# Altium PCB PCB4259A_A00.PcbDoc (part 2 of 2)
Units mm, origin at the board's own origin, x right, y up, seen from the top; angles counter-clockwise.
Board outline 30 x 45 mm, 4 copper layers (Top Layer, Signal Layer 2, Signal Layer 3, Bottom Layer), stack 1.606 mm thick; 90 components, 88 nets, 336 pads, 378 vias.
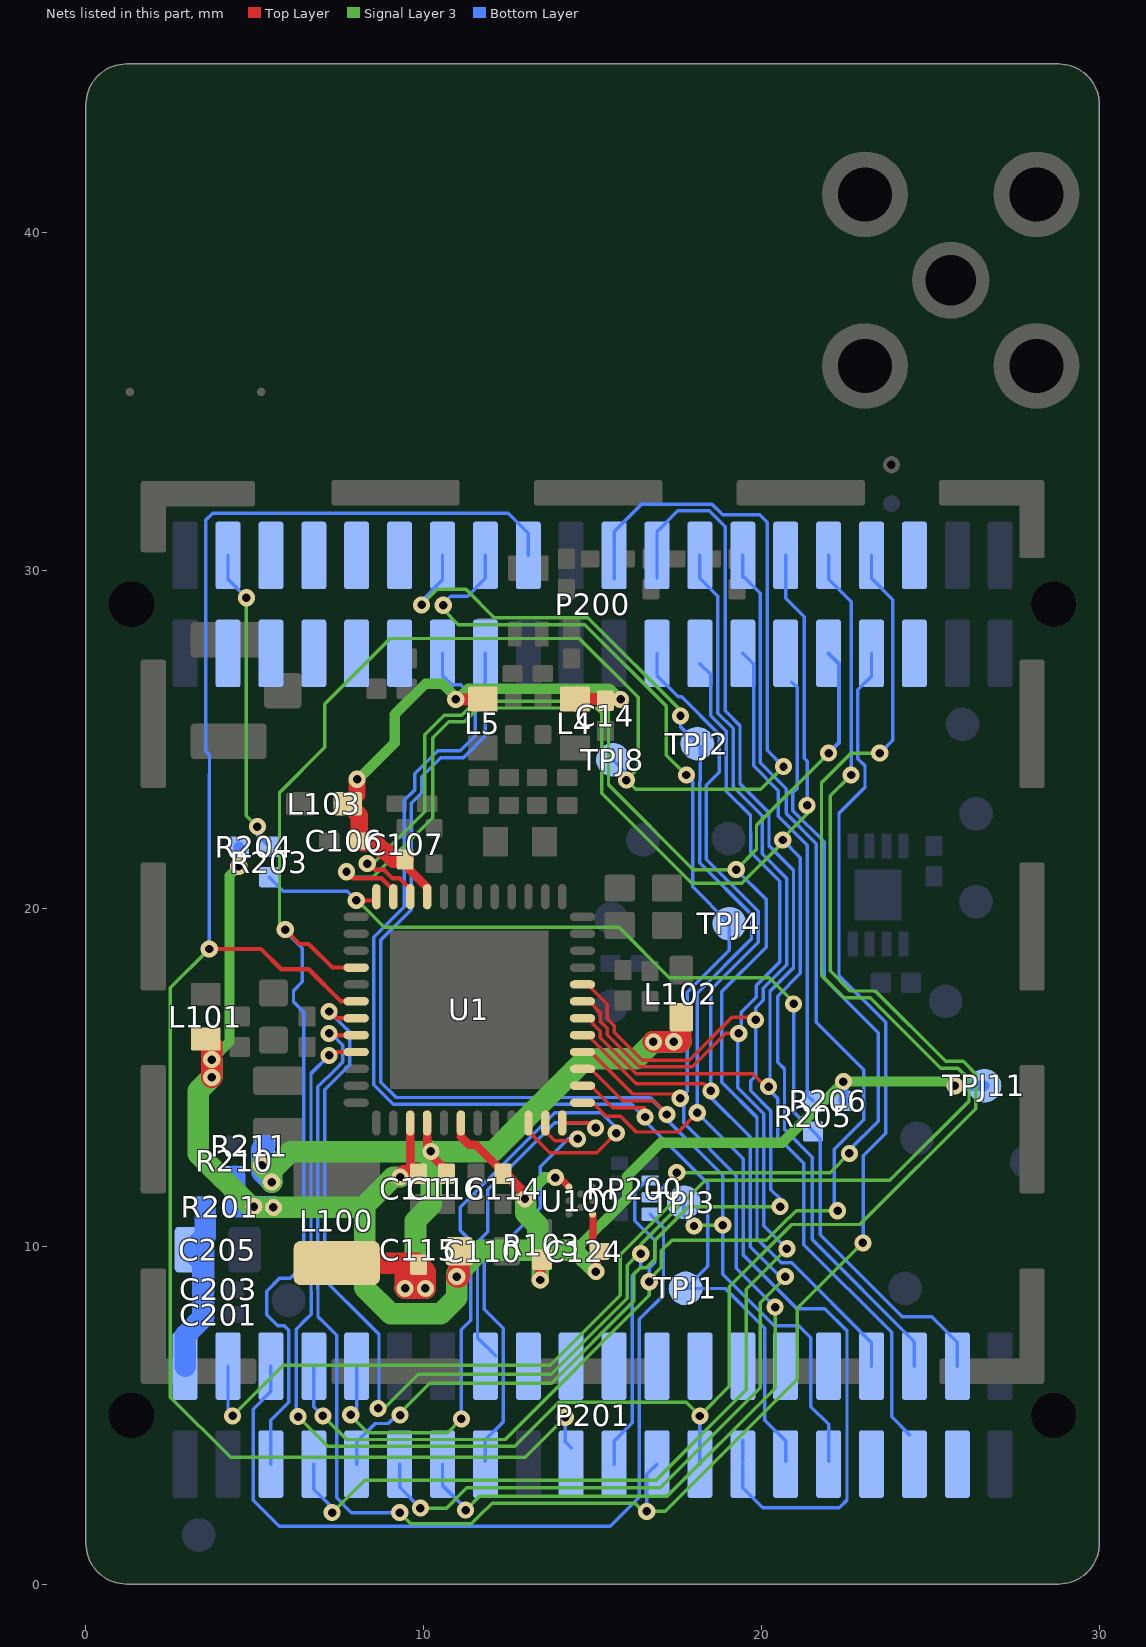
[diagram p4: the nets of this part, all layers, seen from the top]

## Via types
v1: diameter 0.508, hole 0.25, Top Layer to Bottom Layer, tented both sides, 376 vias
v2: diameter 0.5, hole 0.25, Top Layer to Bottom Layer, tented both sides, 2 vias

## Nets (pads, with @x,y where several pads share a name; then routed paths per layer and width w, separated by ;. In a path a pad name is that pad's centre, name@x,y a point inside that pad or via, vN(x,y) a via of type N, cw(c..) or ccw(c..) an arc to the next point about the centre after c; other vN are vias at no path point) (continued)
RADIO_PA3: P200.22 P201.5 TPJ8.1 U1.28 | length 61
  Top Layer w0.102: v1(16,23.8) 16.15,23.8 v1@16.187,23.763
  Top Layer w0.127: v1(5.9,19.375) 6.325,18.95 6.598,18.95 7.298,18.25 U1.28@8,18.25
  Signal Layer 3 w0.102: v1(5.9,19.375) 5.73,19.545 5.73,23.43 7.075,24.775 7.075,26.052 9.013,27.991 14.609,27.991 16.35,26.25 16.35,24.15 v1(16,23.8) 16.275,23.525 19.975,23.525 v1(20.65,24.2)
  Bottom Layer w0.102: P201.5@5.475,3.55 5.475,4.855 5.997,5.377 5.997,7.3 ; v1@5.975,19.25 6.406,18.818 6.406,17.831 6.144,17.568 6.144,17.232 6.45,16.925 6.45,9.45 6.052,9.052 5.73,9.052 5.348,8.67 5.348,7.977 5.673,7.652 5.865,7.652 6,7.517 6,7.3 ; TPJ8.1@15.6,24.7 TPJ8.1@15.6,24.4 16.1,23.9 16.1,23.766 16.066,23.8 v1(16,23.8) ; P200.22@15.635,29.765 P200.22@15.635,30.45 15.635,31.16 16.447,31.972 18.533,31.972 18.852,31.652 19.948,31.652 20.171,31.429 20.171,24.679 v1(20.65,24.2)
RADIO_PA5: P200.18 P201.19 U1.30 | length 55.9
  Top Layer w0.127: v1(3.65,18.8) 5.184,18.8 5.784,18.2 6.598,18.2 7.548,17.25 U1.30@8,17.25
  Signal Layer 3 w0.102: v1(3.65,18.8) 2.5,17.65 2.5,5.533 4.283,3.75 13,3.75 v1(14.188,4.938)
  Bottom Layer w0.102: v1(3.65,18.8) 3.65,23.975 3.656,23.982 3.656,24.544 3.55,24.65 3.55,31.5 3.75,31.7 12.5,31.7 13.095,31.105 P200.18@13.095,30.45 ; v1(14.188,4.938) 14.188,4.215 P201.19@14.365,4.038
RADIO_PB11: P200.34 P201.21 U1.31 | length 62.7
  Top Layer w0.127: v1(7.198,16.95) 7.248,16.95 7.448,16.75 U1.31@8,16.75
  Signal Layer 3 w0.102: v1@8.737,5.112 9.837,6.213 13.769,6.213 16.022,8.466 16.022,9.443 16.354,9.775 v1(16.426,9.775) 16.426,10.051 18.327,11.952 23.8,11.952 26.14,14.292 26.14,14.95 25.815,15.275 25.3,15.275 23.222,17.353 22.447,17.353 21.775,18.025 21.775,23.727 22.648,24.6 v1(23.5,24.6)
  Bottom Layer w0.102: v1(7.198,16.95) 7.604,16.544 7.606,16.544 7.808,16.342 7.808,15.37 7.075,14.638 7.075,8.998 7.711,8.361 7.714,8.361 8.675,7.4 8.675,5.225 v1(8.65,5.2) ; P201.21@15.635,3.55 15.635,4.235 16.175,4.775 16.175,9.125 16.426,9.376 v1(16.426,9.775) ; P200.34@23.255,30.45 23.255,29.771 23.881,29.145 23.881,24.981 v1(23.5,24.6)
RADIO_PB12: P200.33 P201.23 U1.32 | length 56.6
  Top Layer w0.127: v1(7.198,16.3) 7.248,16.25 U1.32@8,16.25
  Signal Layer 3 w0.102: v1(9.288,2.113) 9.618,1.782 11.407,1.782 11.525,1.9 11.644,2.02 12.022,2.397 16.253,2.397 16.6,2.05 v1(16.6,2.15) 17.15,2.15 21.063,6.062 21.063,8.163 v1(23,10.1)
  Bottom Layer w0.102: v1(7.198,16.3) v1@7.224,16.274 ; v1@7.25,16.3 7.254,16.3 7.604,15.95 7.604,15.454 7.391,15.241 6.865,14.715 6.865,8.747 6.869,8.744 6.869,7.919 7.043,7.744 7.422,7.366 7.422,2.551 7.86,2.113 v1(9.288,2.113) ; v1(16.6,2.15) 16.6,3.245 P201.23@16.905,3.55 ; v1(23,10.1) 23.006,10.106 23.006,12.681 23.675,13.35 23.675,16.625 22.294,18.006 22.294,22.818 23.063,23.588 23.063,24.225 22.853,24.435 22.853,26.478 23.255,26.88 P200.33@23.255,27.55
RADIO_PB13: P200.32 P201.25 U1.33 | length 59.4
  Top Layer w0.127: v1(7.198,15.65) 7.198,15.7 7.148,15.75 U1.33@8,15.75
  Signal Layer 3 w0.102: v1(6.282,4.956) 7.162,4.075 12.69,4.075 14,5.385 17.765,5.385 v1(18.175,4.975) 19.05,5.85 19.05,8.8 20.894,10.644 22.912,10.644 26.344,14.075 26.344,15.1 25.965,15.478 25.447,15.478 23.37,17.556 22.631,17.556 22.036,18.15 22.036,23.336 v1(22.65,23.95)
  Bottom Layer w0.102: v1@6.223,5.086 6.223,7.548 6.499,7.824 6.665,7.99 6.665,8.661 6.662,8.663 6.662,15.114 v1(7.198,15.65) ; P201.25@18.175,3.55 v1(18.175,4.975) ; P200.32@21.985,30.45 21.985,29.741 22.65,29.076 v1(22.65,23.95)
RADIO_PC9: P201.10 U1.46 | length 21.1
  Top Layer w0.102: U1.46@13.1,13.65 13.1,13.4 13.729,12.771 15.119,12.771 v1(15.698,13.35)
  Signal Layer 3 w0.102: v1(7.838,5.013) 7.838,4.988 8.345,4.482 10.707,4.482 v1(11.113,4.888)
  Bottom Layer w0.102: v1(7.838,5.013) 8.015,5.19 P201.10@8.015,6.45 ; v1@11.113,4.934 11.113,7.533 11.387,7.807 11.387,10.163 11.084,10.466 11.084,11.159 13.875,13.95 15.25,13.95 15.698,13.502 v1(15.698,13.35)
RADIO_PC10: P201.15 U1.47 | length 12.6
  Top Layer w0.102: U1.47@13.6,13.65 13.6,13.4 13.877,13.123 14.5,13.123 v1(14.555,13.177)
  Bottom Layer w0.102: P201.15@11.825,3.635 11.825,4.275 12.347,4.797 12.347,7.578 11.794,8.131 11.794,9.494 13.444,11.144 13.444,12.071 13.454,12.082 13.454,12.354 14.277,13.177 v1(14.555,13.177)
RADIO_PC11: P201.16 U1.48 | length 10.4
  Top Layer w0.102: U1.48@14.098,13.65 U1.48@14.1,13.65 14.944,13.65 v1(15.088,13.505)
  Bottom Layer w0.102: P201.16@12.131,6.756 11.59,7.297 11.59,10.115 11.9,10.425 11.9,11.677 13.873,13.65 14.944,13.65 v1(15.088,13.505)
RADIO_PD13: P200.31 P201.34 U1.22 | length 44.8
  Top Layer w0.127: v1(8.325,21.326) 8.372,21.326 8.557,21.142 8.827,21.142 9.079,20.89 9.286,20.89 9.598,20.578 U1.22@9.598,20.35
  Signal Layer 3 w0.102: v1(8.325,21.326) 8.496,21.326 10.033,22.863 10.033,25.146 10.612,25.725 11.122,25.725 11.534,26.137 15.188,26.137 15.469,25.856 15.469,23.656 17.975,21.15 v1(19.25,21.15) 19.85,21.75 19.85,22.465 v1(21.985,24.6)
  Bottom Layer w0.102: v1(19.25,21.15) 20.134,20.266 20.134,18.85 18.825,17.541 18.825,14.853 19.866,13.812 19.866,10.221 20.581,9.506 20.894,9.506 23.255,7.145 P201.34@23.255,6.45
  Bottom Layer w0.127: v1(21.985,24.6) 22.294,24.909 22.294,27.241 P200.31@21.985,27.55
RADIO_PD14: P200.30 P201.36 U1.23 | length 51.6
  Top Layer w0.127: v1(7.713,21.087) 7.906,20.894 8.751,20.894 9.098,20.548 U1.23@9.1,20.35
  Signal Layer 3 w0.102: v1(7.713,21.087) 7.71,21.087 7.7,21.076 7.857,20.92 8.494,20.92 ; 10.25,22.676 8.494,20.92 ; v1(21.35,23.05) 21.35,22.8 20.626,22.076 v1(20.626,22.026) 20.626,21.951 19.418,20.744 17.931,20.744 15.265,23.41 15.265,25.772 15.104,25.934 11.618,25.934 11.206,25.522 10.734,25.522 10.262,25.049 10.262,22.687 8.494,20.92
  Bottom Layer w0.102: v1(20.626,22.026) 21.15,21.502 21.15,18.079 20.475,17.404 20.475,15.45 20.679,15.246 20.679,13.459 21.5,12.638 21.5,10.2 24.525,7.175 P201.36@24.525,6.45 ; P200.30@20.715,30.45 20.715,29.185 21.259,28.641 21.259,25.353 21.26,24.453 21.35,24.362 v1(21.35,23.05)
RADIO_PD15: P201.38 R203.1 R205.1 U1.24 | length 31
  Top Layer w0.127: v1(8,20.238) 8.486,20.238 U1.24@8.598,20.35
  Signal Layer 3 w0.102: v1(8,20.238) 8.03,20.238 8.828,19.439 15.78,19.439 17.271,17.948 20.227,17.948 20.95,17.225 v1(20.95,17.175)
  Bottom Layer w0.102: R203.1@5.425,20.925 5.844,20.506 7.732,20.506 v1(8,20.238) ; v1(20.95,17.175) 20.95,13.975 R205.1@21.525,13.4 21.739,13.186 21.739,10.339 24.164,7.913 25.038,7.913 25.795,7.156 P201.38@25.795,6.45
RADIO_PF0: P200.14 P201.27 TPJ2.1 U1.1 | length 47
  Top Layer w0.102: U1.1@14.698,14.25 U1.1@14.7,14.25 14.998,14.25 15.398,13.85 15.824,13.85 16.292,13.382 17.53,13.382 v1(18.098,13.95)
  Signal Layer 3 w0.102: v1(9.938,28.988) 10.4,29.45 11.25,29.45 12.093,28.607 14.855,28.607 17.6,25.862 v1(17.6,25.7)
  Bottom Layer w0.102: v1(9.938,28.988) 9.938,29.113 10.555,29.73 P200.14@10.555,30.45 ; v1(17.6,25.7) 17.6,25.38 TPJ2.1@18.1,24.88 18.181,24.799 18.181,23.782 18.164,23.765 18.164,21.358 19.702,19.82 19.702,19.1 18.094,17.491 18.094,13.954 v1(18.098,13.95) 19.46,12.588 19.46,9.74 21.05,8.15 21.877,8.15 22.529,7.498 22.529,2.488 22.304,2.263 20.038,2.263 19.445,2.856 P201.27@19.445,3.55 ; P201.27@19.445,3.635 P201.27@19.445,4.255
RADIO_PF1: P200.13 P201.29 TPJ1.1 U1.2 | length 38.6
  Top Layer w0.102: U1.2@14.7,14.75 14.948,14.75 15.598,14.1 16.548,14.1
  Bottom Layer w0.102: 9.725,23.975 9.731,23.981 ; P200.13@10.555,27.55 10.555,26.885 10.82,26.619 11.1,26.619 11.525,26.194 11.525,25.114 11.074,24.663 10.413,24.663 9.731,23.981 ; v1@16.548,13.8 16.548,13.715 18.406,11.857 18.406,9.406 TPJ1.1@17.75,8.75 18.926,8.75 20.1,7.576 20.1,4.85 20.715,4.235 P201.29@20.715,3.635 ; v1@16.55,13.8 16.15,14.2 9.1,14.2 8.525,14.775 8.525,19.15 9.425,20.05 9.425,23.2 9.731,23.507 9.731,23.981
  other v1: 16.551,13.826
RADIO_PF2: P200.15 P201.31 TPJ3.1 U1.3 | length 40.7
  Top Layer w0.102: U1.3@14.7,15.25 14.948,15.25 15.895,14.303 16.797,14.303 v1(17.2,13.9)
  Signal Layer 3 w0.102: v1(18,10.6) 18.029,10.629 18.033,10.625 v1(18.85,10.625)
  Bottom Layer w0.102: P200.15@11.825,27.55 11.825,25.109 11.176,24.46 10.498,24.46 9.935,23.897 9.935,23.422 9.628,23.116 9.628,19.966 8.728,19.066 8.728,14.859 9.184,14.403 16.697,14.403 ; 16.75,14.35 16.697,14.403 ; TPJ3.1@17.7,11.3 17.7,10.9 v1(18,10.6) ; P201.31@21.985,3.635 21.985,4.725 21.463,5.248 21.463,7.295 21.105,7.652 20.373,7.652 18.85,9.175 v1(18.85,10.625) 18.85,12.1 17.2,13.75 v1(17.2,13.9) 16.697,14.403
RADIO_PF3: P200.16 P201.13 TPJ4.1 U1.4 | length 48.7
  Top Layer w0.102: U1.4@14.698,15.75 U1.4@14.7,15.75 14.948,15.75 16.192,14.506 17.466,14.506 v1(17.593,14.38)
  Signal Layer 3 w0.102: v1(10.576,28.976) 10.576,28.855 11.027,28.404 14.771,28.404 17.182,25.993 17.182,24.534 17.766,23.95 v1(17.775,23.95) ; v1(11.238,2.188) 11.65,2.6 17.2,2.6 20.4,5.8 v1(20.4,8.2)
  Bottom Layer w0.102: P201.13@10.555,3.55 10.555,2.918 11.238,2.235 v1(11.238,2.188) ; v1(10.576,28.976) 10.576,29.025 10.798,29.248 11.298,29.248 11.825,29.775 P200.16@11.825,30.45 ; v1(17.775,23.95) 17.775,23.941 17.961,23.755 17.961,20.639 TPJ4.1@19.05,19.55 19.05,18.769 17.806,17.525 17.806,14.593 v1(17.593,14.38) 17.692,14.281 17.692,13.65 19.256,12.085 19.256,9.344 v1(20.4,8.2)
RADIO_PF4: P200.23 P201.11 U1.5 | length 42.9
  Top Layer w0.102: U1.5@14.698,16.25 U1.5@14.7,16.25 14.85,16.25 16.285,14.815 18.285,14.815 v1(18.5,14.6)
  Signal Layer 3 w0.102: v1(9.9,2.25) 10.675,2.25 11.275,2.85 17,2.85 19.957,5.807 19.957,8.331 20.725,9.1 v1(20.7,9.1)
  Bottom Layer w0.102: P201.11@9.285,3.55 9.285,2.865 v1(9.9,2.25) ; P200.23@16.905,27.55 16.905,26.895 17.531,26.269 17.633,26.269 18.752,25.15 18.752,24.029 18.368,23.644 18.368,21.458 19.906,19.92 19.906,19 18.5,17.594 v1(18.5,14.6) ; v1@18.504,14.6 18.504,14.4 19.663,13.242 19.663,9.987 20.55,9.1 v1(20.7,9.1)
RADIO_PF5: P200.24 P201.35 U1.6 | length 40.1
  Top Layer w0.102: U1.6@14.8,16.8 14.9,16.8 15,16.7 15,16.592 15.227,16.365 15.227,16.173 16.295,15.105 19.745,15.105 20.124,14.726 v1(20.209,14.726)
  Bottom Layer w0.102: P200.24@16.905,29.771 P200.24@16.905,30.45 16.905,31.155 17.519,31.769 18.449,31.769 18.923,31.295 18.923,25.852 19.362,25.413 19.362,23.688 20.22,22.83 20.22,21.855 20.947,21.128 20.947,18.247 20.251,17.551 20.251,14.769 v1(20.209,14.726) 20.209,14.641 20.476,14.374 20.476,13.225 21.247,12.453 21.247,10.05 23.849,7.449 23.849,4.952 P201.35@24.388,4.413
RADIO_PF6: P200.25 P201.7 U1.7 | length 45.6
  Top Layer w0.102: U1.7@14.698,17.25 U1.7@14.7,17.25 14.898,17.25 15.227,16.921 15.227,16.652 15.431,16.449 15.431,16.257 16.379,15.308 17.946,15.308 18.937,16.3 v1(19.325,16.3)
  Signal Layer 3 w0.102: v1(7.285,2.113) 8.247,3.075 16.875,3.075 19.55,5.75 19.55,8.725 v1(20.75,9.925)
  Bottom Layer w0.102: P201.7@6.745,3.55 6.745,2.805 7.285,2.265 v1(7.285,2.113) ; P200.25@18.175,27.25 18.494,26.931 18.494,25.706 18.956,25.244 18.956,23.47 19.672,22.753 19.672,22.253 19.675,22.25 19.675,21.669 20.54,20.803 20.54,18.415 19.845,17.719 19.845,17.37 19.4,16.925 19.4,16.375 v1(19.325,16.3) 19.29,16.265 19.29,14.697 20.069,13.919 20.069,10.606 v1(20.75,9.925)
RADIO_PF7: P200.26 P201.9 U1.8 | length 45.3
  Top Layer w0.102: v1@9.25,5.05 v1(9.3,5) ; U1.8@14.7,17.75 14.842,17.75 15.431,17.162 15.431,16.736 15.634,16.533 15.634,16.341 16.463,15.512 17.862,15.512 19.125,16.775 19.75,16.775 v1(19.825,16.7)
  Signal Layer 3 w0.102: v1(9.3,5) 9.3,5.071 10.179,5.95 13.794,5.95 16.225,8.381 16.225,9.187 16.407,9.369 16.594,9.369 16.832,9.607 16.832,10.17 17.837,11.175 v1(20.55,11.175) ; v1@19.625,16.7 v1(19.825,16.7)
  Bottom Layer w0.102: P201.9@8.015,3.55 8.015,4.209 8.559,4.752 8.952,4.752 9.2,5 v1(9.3,5) ; P200.26@18.175,30.45 18.175,29.776 18.706,29.245 18.706,25.781 19.159,25.329 19.159,23.604 20.016,22.746 20.016,21.615 20.744,20.887 20.744,18.331 20.048,17.635 20.048,17.286 19.825,17.063 v1(19.825,16.7) 19.825,15.05 19.675,14.9 19.675,14.6 20.272,14.003 20.272,11.678 20.55,11.4 v1(20.55,11.175)
USB_VBUS: P200.35
USB_VREG: P200.36
VBIAS: C14.1 C106.1 C107.1 L4.1 L5.1 L103.2 U1.21 | length 17.1
  Top Layer w0.254: C107.1@9.386,21.337 10.098,20.625 U1.21@10.098,20.35
  Top Layer w0.356: v1(10.947,26.187) L5.1@11.563,26.187 ; L4.1@14.475,26 L4.1@14.575,26.1 ; L4.1@14.475,26.2 15.325,26.2 C14.1@15.375,26.15 ; C14.1@15.375,26.188 v1(15.828,26.188)
  Top Layer w0.508: v1(8.025,23.825) 8.025,23.375 L103.2@7.75,23.1 8.09,22.76 8.09,22.01 C106.1@8.1,22 8.164,21.936 8.578,21.936 8.819,21.694 8.867,21.694 9.112,21.45 C107.1@9.45,21.45
  Signal Layer 3 w0.305: v1@8.066,23.825 9.144,24.902 9.144,25.744 10.052,26.652 10.555,26.652 v1@10.954,26.253 ; v1(10.947,26.187) 10.997,26.187 11.31,26.5 15.5,26.5 v1@15.91,26.089
VDCDC: C115.1 C116.1 L100.2 L102.1 R211.2 U1.40 | length 29.2
  Top Layer w0.254: U1.40@10.098,13.65 v1@10.098,12.821 ; v1(10.21,12.806) 10.194,12.821 v1@10.098,12.821 ; C116.1@10.675,12.15 10.675,12.244 v1@10.098,12.821
  Top Layer w0.635: L100.2@7.398,9.5 C115.1@9.798,9.5 ; v1(16.8,16.05) 17.602,16.05 17.602,16.749 L102.1@17.628,16.775 ; C115.1@9.798,9.5 10.048,9.25 v1(10.048,8.75) v1(9.448,8.75) 9.448,9.15 C115.1@9.798,9.5
  Signal Layer 3 w0.635: v1(5.2,12.4) v1@5.5,12.1 ; v1(5.5,11.9) v1@5.5,12.1 ; v1@10.003,8.795 9.748,9.05 ; v1(10.048,8.75) v1(9.448,8.75) 9.748,9.05 ; v1@10.225,12.806 v1@10.225,12.8 ; v1@17.629,16.05 v1(16.8,16.05) 16.3,15.55 14.798,15.55 12.948,13.7 12.048,12.8 v1@10.225,12.8 ; v1@5.5,12.1 5.5,12.25 6.05,12.8 v1@10.225,12.8 ; 9.748,9.05 9.748,10.748 10.225,11.225 v1@10.225,12.8
  Bottom Layer w0.635: R211.2@5.3,12.975 5.2,12.875 v1(5.2,12.4) 5.2,12.2 v1(5.5,11.9)
  other v1: 17.399,16.053
VMCU: C110.1 C111.1 C114.1 C124.1 L101.1 R103.1 R201.2 R204.1 R206.1 R210.2 TPJ11.1 U1.39 U1.42 U100.A1 U100.E3 | length 59
  Top Layer w0.203: v1(13.898,12.034) 14.014,12.034 U100.E3@14.298,11.75 ; U100.A1@14.998,10.95 15.01,10.938 15.01,10.281 14.998,10.269 14.998,9.95 C124.1@15.098,9.85
  Top Layer w0.254: U1.39@9.598,13.65 9.598,12.4 C111.1@9.848,12.15 ; U1.42@11.098,13.65 11.098,13.25 11.348,13 11.548,13 C114.1@12.348,12.2
  Top Layer w0.305: C114.1@12.348,12.2 12.998,11.55 v1(12.998,11.4) ; v1(13.45,9) 13.45,9.55 R103.1@13.5,9.6 ; v1(15.098,9.25) C124.1@15.098,9.85
  Top Layer w0.508: v1(9.298,12.05) 9.398,12.15 C111.1@9.848,12.15
  Top Layer w0.635: L101.1@3.55,16.135 3.725,15.96 v1(3.725,15.525) v1(3.725,15) ; v1(10.976,9.1) 11.05,9.1 C110.1@11.05,9.85
  Signal Layer 3 w0.305: v1(3.725,15.525) 4.25,16.05 4.25,20.975 v1(4.525,21.25) ; 13.4,9.875 13.45,9.825 ; 14.473,9.875 16.025,11.427 16.025,12.075 17.011,13.061 20.611,13.061 v1(22.425,14.875) 25.6,14.875 v1(25.725,14.75)
  Signal Layer 3 w0.33: v1(12.998,11.4) 12.998,11.464 13.568,12.034 v1(13.898,12.034)
  Signal Layer 3 w0.508: v1(13.45,9) 13.45,9.825 ; 14.473,9.875 v1(15.098,9.25)
  Signal Layer 3 w0.635: v1(3.725,15.525) v1(3.725,15) 3.325,14.6 3.325,12.733 4.883,11.175 v1(4.975,11.175) 5,11.15 v1(5.55,11.15) 8.196,11.15 8.248,11.202 ; v1(9.298,12.05) 9.096,12.05 8.248,11.202 ; v1(12.998,11.4) 13.021,11.377 13.021,10.977 13.375,10.623 13.375,10.221 13.4,10.196 13.4,9.875 ; 14.473,9.875 13.4,9.875 ; 8.248,11.202 8.248,8.775 9.023,8 10.5,8 10.976,8.476 v1(10.976,9.1) 10.976,9.176 11.675,9.875 13.4,9.875
  Bottom Layer w0.305: v1(4.525,21.25) R204.1@4.525,21.825 ; R206.1@22.425,14.3 v1(22.425,14.875) ; v1(25.725,14.75) TPJ11.1@26.6,14.75
  Bottom Layer w0.635: R210.2@4.4,12.075 4.4,11.2 R201.2@4.425,11.175 v1(4.975,11.175) ; v1@5.073,11.175 v1(4.975,11.175) ; v1(5.55,11.15) 5.537,11.163 4.975,11.163 v1(4.975,11.175)
VMCU_IN: C201.1 C203.1 C205.1 P201.2 R201.1 | length 7.3
  Bottom Layer w0.635: P201.2@2.935,6.45 2.935,7.36 C201.1@3.488,7.913 ; 3.488,8.275 C201.1@3.488,7.913 ; C205.1@3.5,10.25 3.488,10.238 3.488,8.688 C203.1@3.463,8.663 ; R201.1@3.525,11.175 3.525,10.3 3.1,9.875 3.463,9.512 C203.1@3.463,8.663 ; C203.1@3.463,8.663 3.463,7.938 C201.1@3.488,7.913
WSTK_F14: P200.27 R205.2 R206.2 | length 14.1
  Bottom Layer w0.102: P200.27@19.445,27.55 19.764,27.231 19.764,24.223 20.5,23.488 20.5,22.727 21.353,21.874 21.353,17.403 21.356,17.4 21.356,14.469 R205.2@21.525,14.3
WSTK_F15: P200.28 P201.8 RP200.6 | length 45.4
  Signal Layer 3 w0.102: v1(7.015,4.979) 7.716,4.278 12.409,4.278 16.676,8.545 v1(16.676,8.95) 16.676,9.014 17.035,9.373 17.035,9.86 17.35,10.175 20.138,10.175 20.809,10.847 20.822,10.847 21.025,11.05 v1(22.25,11.05)
  Bottom Layer w0.102: P201.8@6.745,6.45 6.745,5.249 v1(7.015,4.979) ; v1(16.676,8.95) 16.676,9.351 16.832,9.507 16.832,10.176 16.25,10.758 16.25,11.598 16.602,11.95 RP200.6@16.7,11.95 ; P200.28@19.445,29.806 P200.28@19.445,29.855 ; P200.28@19.445,30.45 P200.28@19.445,29.855 ; v1(22.25,11.05) 22.15,11.15 22.15,12.875 23.025,13.75 23.025,15.225 21.625,16.625 21.625,21.913 20.727,22.811 20.727,23.548 19.967,24.308 19.967,29.333 P200.28@19.445,29.855
WSTK_F16: P200.29 P201.4 RP200.7 | length 40.7
  Signal Layer 3 w0.102: v1(4.34,4.979) 5.843,6.482 13.751,6.482 15.819,8.55 15.819,9.743 17.491,11.415 v1(17.491,12.179) 22.029,12.179 v1(22.6,12.75)
  Bottom Layer w0.102: P201.4@4.205,6.45 4.205,5.114 v1(4.34,4.979) ; RP200.7@16.7,11.45 16.798,11.45 17.137,11.789 17.137,11.825 v1(17.491,12.179) ; P200.29@20.9,26.7 21.056,26.544 21.056,25.269 ; 21.056,25.269 21.056,23.552 20.93,23.425 20.93,22.895 21.85,21.975 21.85,17.915 23.45,16.315 23.45,13.7 22.6,12.85 v1(22.6,12.75)
WSTK_P3: P201.6 RP200.8 | length 25.1
  Bottom Layer w0.102: P201.6@5.475,6.45 5.475,5.7 4.953,5.178 4.953,2.48 5.726,1.707 15.525,1.707 16.383,2.564 16.383,7.833 17.098,8.548 17.098,10.552 RP200.8@16.7,10.95
WSTK_P15: P201.18
WSTK_P17: P201.20
WSTK_P19: P201.22
WSTK_P21: P201.24
WSTK_P23: P201.26
WSTK_P25: P201.28
WSTK_P27: P201.30
WSTK_P29: P201.32
WSTK_P30: P201.33
WSTK_P34: P201.37
WSTK_P36: P200.3
WSTK_P37: P200.4 R203.2 R204.2 | length 9.1
  Signal Layer 3 w0.102: v1(4.75,29.2) 4.75,22.75 v1(5.075,22.425)
  Bottom Layer w0.102: P200.4@4.205,30.45 4.205,29.745 v1(4.75,29.2) ; v1(5.075,22.425) 5.075,22.175 R204.2@5.425,21.825
WSTK_P38: P200.5
WSTK_P39: P200.6
WSTK_P40: P200.7
WSTK_P41: P200.8
WSTK_P42: P200.9
WSTK_P43: P200.10
WSTK_P44: P200.11
WSTK_P45: P200.12
pads on no net: P200.M1 P200.M2 P201.40 P201.M1 P201.M2 RP200.4 RP200.5 TPJ9.1 TPJ18.1 TPJ19.1 TPJ20.1 U1.49@10.2,15.85 U1.49@10.2,18.15 U1.49@12.5,15.85 U1.49@12.5,18.15 U100.C1 U200.9
copper on no net:
  other v1: 22.175,28.975

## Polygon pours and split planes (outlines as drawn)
GND on Top Layer "GND_L1" (solid, remove dead copper, pour order 29): 0.605,34.64 20.99,34.64 ccw(c20.99,35.507) 21.857,35.507 21.857,40.54 23.657,42.34 27.557,42.34 29.357,40.54 29.355,1.155 cw(c28.79,1.155) 28.79,0.59 1.255,0.595 cw(c1.255,1.245) 0.605,1.245
GND on Signal Layer 2 "GND_L2" (solid, remove dead copper, pour order 27): 0.605,34.64 20.99,34.64 ccw(c20.99,35.507) 21.857,35.507 21.857,40.54 23.657,42.34 27.557,42.34 29.357,40.54 29.355,1.155 cw(c28.79,1.155) 28.79,0.59 1.255,0.595 cw(c1.255,1.245) 0.605,1.245
GND on Signal Layer 3 "GND_L3" (solid, remove dead copper, pour order 25): 0.605,34.64 20.99,34.64 ccw(c20.99,35.507) 21.857,35.507 21.857,40.54 23.657,42.34 27.557,42.34 29.357,40.54 29.355,1.155 cw(c28.79,1.155) 28.79,0.59 1.255,0.595 cw(c1.255,1.245) 0.605,1.245
GND on Bottom Layer "GND_L4" (solid, remove dead copper, pour order 24): 0.605,34.64 20.99,34.64 ccw(c20.99,35.507) 21.857,35.507 21.857,40.54 23.657,42.34 27.557,42.34 29.357,40.54 29.355,1.155 cw(c28.79,1.155) 28.79,0.59 1.255,0.595 cw(c1.255,1.245) 0.605,1.245

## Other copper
Top Layer:
  rectangle net GND: 16.1,28.5 17.5,29.6
  rectangle net GND: 18.675,28.8 20,29.6
  pour cut-out: 10.9,23.031 10.9,25.294 10.819,25.375 10.819,27.1 11.219,27.1 11.219,28.9 12,28.9 12,31.1 20,31.1 20,29.6 14.85,29.6 14.85,24.82 15.15,24.82 15.15,20.056 14.119,20.056 14.119,14.056 10.244,14.056 10.292,10.796 8.119,10.796 8.119,23.031
Signal Layer 2:
  pour cut-out: 3.047,27.306 3.047,25.606 5.129,25.606 5.129,25.874 6.425,25.875 6.425,27.044 5.13,27.044 5.13,27.305
  pour cut-out: 11.735,20.091 11.735,21.438 11.151,22.098 11.151,25.248 11.151,25.552 cw(c11.267,25.551) 11.185,25.634 cw(c11.37,25.434) 11.349,25.706 11.365,25.706 14.83,25.708 cw(c14.829,25.482) 14.911,25.693 cw(c14.86,25.495) 14.979,25.661 15.016,25.634 cw(c14.812,25.353) 15.152,25.424 15.152,20.477 cw(c14.47,20.522) 14.418,19.84 13.214,19.844 11.966,19.84 cw(c11.964,20.109) 11.861,19.861 cw(c11.986,20.088) 11.759,19.963
Signal Layer 3:
  pour cut-out: 11.735,20.091 11.735,21.438 11.151,22.098 11.151,25.248 11.151,25.552 cw(c11.267,25.551) 11.185,25.634 cw(c11.37,25.434) 11.349,25.706 11.365,25.706 14.83,25.708 cw(c14.829,25.482) 14.911,25.693 cw(c14.86,25.495) 14.979,25.661 15.016,25.634 cw(c14.812,25.353) 15.152,25.424 15.152,20.477 cw(c14.47,20.522) 14.418,19.84 13.214,19.844 11.966,19.84 cw(c11.964,20.109) 11.861,19.861 cw(c11.986,20.088) 11.759,19.963
Bottom Layer:
  pour cut-out: 23.845,33.935 cw(c23.845,33.135) 24.645,33.135 cw(c23.845,33.135) 23.845,32.335 cw(c23.845,33.135) 23.045,33.135 cw(c23.845,33.135)

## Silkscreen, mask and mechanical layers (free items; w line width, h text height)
Top Overlay:
  text ".CreativeName" at 1,41.4 h3.85
  text ".2G4freq" at 0.7,39 h1.9
  text ".SubGfreq" at 13.5,39 h1.9
  text ".2G4power" at 0.7,37 h1.9
  text ".SubGpower" at 13.5,37 h1.9
  text ".ProcessorType" at 10.5,7.5 h1.9
Bottom Overlay:
  lines w0.152: 3.95,11.925 3.95,11.625 4.25,11.625 ; 3.95,13.175 3.95,13.475 4.25,13.475 ; 4.075,21.65 4.075,21.35 4.375,21.35 ; 4.075,22 4.075,22.3 4.375,22.3 ; 4.6,11.625 4.9,11.625 4.9,11.925 ; 4.625,21.35 4.925,21.35 4.925,21.05 ; 4.9,12.175 4.9,12.475 5.2,12.475 ; 4.925,20.75 4.925,20.425 5.225,20.425 ; 5.5,12.475 5.825,12.475 5.825,12.775 ; 5.5,13.475 5.825,13.475 5.825,13.175 ; 5.625,20.425 5.925,20.425 5.925,20.75 ; 5.625,22.3 5.925,22.3 5.925,22 ; 21.075,13.25 21.075,12.95 21.375,12.95 ; 21.075,14.5 21.075,14.8 21.375,14.8 ; 21.725,12.95 22.025,12.95 22.025,13.25 ; 22.025,13.5 22.025,13.8 22.325,13.8 ; 22.625,13.8 22.95,13.8 22.95,14.1 ; 22.625,14.8 22.95,14.8 22.95,14.5
  text "BOARD INFO" at 20.55,43.35 h1.6
  text "'.BoardName' Rev. '.BoardRevision'" at 28.6,26 h1.52 r90
  text "Sensor Enable" at 9.55,22.825 h1.6
  text "ON" at 3.8,21.475 h1.2
  text "PD15" at 8.7,21.325 h1.2
  text "Disp Enable" at 25.275,15.125 h1.6
  text "ON" at 24.6,13.95 h1.2
  text "PAVDD" at 6.6,13.85 h1.6
  text "PD15" at 20.701,13.589 h1.2
  text "VDCDC" at 9.6,12.6 h1.2
  text "VMCU" at 3.825,12.45 h1.2
Top Solder:
  the board outline again, w1
Bottom Solder:
  the board outline again, w1
BOARD OUTLINE 1:
  the board outline again, w0.1
Mechanical 2:
  lines w0.1: -0.5,0 0.5,0 ; 0,-0.5 0,0.5
Mechanical 11:
  the board outline again, w0.1
Mechanical 12:
  the board outline again, w0.1
EXT_SILKP 20:
  lines w0.152: 3.95,11.925 3.95,11.625 4.25,11.625 ; 3.95,13.175 3.95,13.475 4.25,13.475 ; 4.075,21.65 4.075,21.35 4.375,21.35 ; 4.075,22 4.075,22.3 4.375,22.3 ; 4.6,11.625 4.9,11.625 4.9,11.925 ; 4.625,21.35 4.925,21.35 4.925,21.05 ; 4.9,12.175 4.9,12.475 5.2,12.475 ; 4.925,20.75 4.925,20.425 5.225,20.425 ; 5.5,12.475 5.825,12.475 5.825,12.775 ; 5.5,13.475 5.825,13.475 5.825,13.175 ; 5.625,20.425 5.925,20.425 5.925,20.75 ; 5.625,22.3 5.925,22.3 5.925,22 ; 21.075,13.25 21.075,12.95 21.375,12.95 ; 21.075,14.5 21.075,14.8 21.375,14.8 ; 21.725,12.95 22.025,12.95 22.025,13.25 ; 22.025,13.5 22.025,13.8 22.325,13.8 ; 22.625,13.8 22.95,13.8 22.95,14.1 ; 22.625,14.8 22.95,14.8 22.95,14.5
  lines w0.154: 1.5,38 1.5,37 2.5,37 ; 1.5,42 1.5,43 2.5,43 ; 19.5,37 20.5,37 20.5,38 ; 19.5,43 20.5,43 20.5,42
  text "BOARD INFO" at 20.55,43.35 h1.52
  text "Sensor Enable" at 9.45,22.85 h1.52
  text "ON" at 3.8,21.475 h1.14
  text "WSTK_P37" at 11.475,21.025 h1.14
  text "Disp Enable" at 25.275,15.125 h1.52
  text "ON" at 24.6,13.95 h1.14
  text "PAVDD" at 6.85,13.9 h1.52
  text "WSTK_P35" at 20.95,13.475 h1.14
  text "VDCDC" at 9.6,12.6 h1.14
  text "VMCU" at 3.825,12.15 h1.14
Mechanical 26:
  lines w0.2: -125.405,-47.962 -120.405,-47.962 ; -125.405,-0.962 -120.405,-0.962 ; -125.393,46.038 -120.405,46.038 ; -54.197,-94.993 -54.197,-89.993 ; -54.197,90.007 -54.197,95.007 ; 17.103,-94.993 17.103,-89.993 ; 17.103,90.007 17.103,95.007 ; 88.303,-94.993 88.303,-89.993 ; 88.303,90.007 88.303,95.007 ; 154.595,-47.962 159.595,-47.962 ; 154.595,-0.962 159.595,-0.962 ; 154.595,46.038 159.583,46.038 ; -125.393,-94.993 159.595,-94.993 159.595,94.999 -125.393,94.999 -125.393,-94.993 ; -120.405,-89.993 154.595,-89.993 154.595,90.007 -120.405,90.007 -120.405,-89.993
  text "1" at -92.505,91.578 h1.52
  text "2" at -20.197,91.578 h1.52
  text "3" at 52.403,91.578 h1.52
  text "4" at 123.203,91.578 h1.52
  text "D" at 156.593,72.438 h1.52
  text "D" at -123.518,71.233 h1.52
  text "C" at -123.518,23.738 h1.52
  text "C" at 156.466,23.738 h1.52
  text "B" at -123.518,-23.862 h1.52
  text "B" at 156.466,-23.862 h1.52
  text "A" at -123.518,-71.362 h1.52
  text "A" at 156.466,-71.362 h1.52
  text "1" at -91.285,-93.435 h1.52
  text "2" at -20.197,-93.435 h1.52
  text "3" at 52.103,-93.435 h1.52
  text "4" at 122.803,-93.435 h1.52
Mechanical 27:
  circle w0.254: c38.623,-82.995 r2.962
  circle w0.152: c70.608,-68.539 r1.778
  circle w0.152: c70.608,-68.539 r0.762
  lines w0.152: 59.609,-68.539 66.975,-68.539 ; 68.322,-68.539 72.894,-68.539 ; 60.371,-69.301 60.371,-67.777 66.213,-66.761 66.188,-70.317 60.371,-69.301
  lines w0.2: 34.575,-89.929 34.575,-63.069 74.589,-63.069 ; 34.575,-75.705 154.539,-75.705 ; 34.589,-72.069 74.589,-72.069 ; 54.869,-89.878 54.869,-75.781 ; 54.869,-72.022 54.869,-63.107 ; 134.589,-75.68 134.589,-72.069 ; 144.589,-72.069 144.589,-63.069 ; 154.589,-72.069 74.589,-72.069 ; 154.589,-63.069 74.589,-63.069 ; 74.589,-72.069 74.589,-63.069
  text "SIZE" at 36.589,-65.069 h1.52
  text "DOC NO" at 76.589,-65.069 h1.52
  text "REV" at 146.589,-65.069 h1.52
  text "PROJECTION" at 55.885,-65.418 h1.52
  text "'.ProjectRevision'" at 146.309,-69.99 h2.54
  text "A4" at 39.239,-70.444 h2.54
  text "PCB4259" at 79.088,-70.444 h2.54
  text "REF" at 36.589,-74.069 h1.52
  text "SHEET" at 135.589,-74.069 h1.52
  text "1 of 2" at 145.43,-75.106 h1.52
  text "This drawing is confidential and is supplied on the express" at 55.352,-78.677 h1.52
  text "condition that it shall not be loaned, copied or disclosed to any" at 55.352,-81.217 h1.52
  text "other person or used for any purpose without the written consent of" at 55.352,-83.757 h1.52
  text "C" at 38.029,-84.011 h2.03
  text "2017" at 43.109,-84.163 h2.54
  text "SILICON LABS" at 55.784,-88.05 h2.54
Mechanical 28:
  lines w0.2: -125.404,-47.963 -120.404,-47.963 ; -125.404,-0.963 -120.404,-0.963 ; -125.392,46.037 -120.404,46.037 ; 154.596,-47.963 159.596,-47.963 ; 154.596,46.037 159.596,46.037
  lines w0.203: -120.429,-89.995 -120.429,90.005 ; -120.404,-89.995 154.596,-89.995 154.596,90.005 -120.404,90.005 ; -54.196,-94.995 -54.196,-89.995 ; -54.196,90.005 -54.196,95.005 ; 17.104,-94.995 17.104,-89.995 ; 17.104,90.005 17.104,95.005 ; 88.304,-94.995 88.304,-89.995 ; 88.304,90.005 88.304,95.005 ; -125.392,-94.995 159.596,-94.995 159.596,94.997 -125.392,94.997 -125.392,-94.995
  text "4" at -91.487,91.577 h1.52
  text "3" at -19.18,91.577 h1.52
  text "2" at 53.42,91.577 h1.52
  text "1" at 124.22,91.577 h1.52
  text "D" at 157.61,72.437 h1.52
  text "D" at -122.501,71.232 h1.52
  text "C" at -122.501,23.737 h1.52
  text "C" at 157.61,22.137 h1.52
  text "B" at -122.501,-23.863 h1.52
  text "B" at 157.61,-24.963 h1.52
  text "A" at 156.592,-71.287 h1.52
  text "A" at -122.501,-71.363 h1.52
  text "A" at 157.483,-71.363 h1.52
  text "4" at -90.268,-93.437 h1.52
  text "3" at -19.18,-93.437 h1.52
  text "2" at 52.967,-93.437 h1.52
  text "1" at 123.82,-93.437 h1.52
Mechanical 29:
  circle w0.254: c-4.266,-83.059 r2.962
  circle w0.152: c-36.251,-68.603 r1.778
  circle w0.152: c-36.251,-68.603 r0.762
  lines w0.152: -38.537,-68.603 -33.965,-68.603 ; -32.619,-68.603 -25.253,-68.603 ; -31.857,-66.825 -26.015,-67.841 -26.015,-69.365 -31.831,-70.381 -31.857,-66.825
  lines w0.2: -120.232,-72.134 -40.232,-72.134 ; -120.232,-63.134 -40.232,-63.134 ; -120.182,-75.769 -0.218,-75.769 ; -110.232,-72.134 -110.232,-63.134 ; -100.232,-75.744 -100.232,-72.134 ; -20.512,-89.943 -20.512,-75.846 ; -20.512,-72.086 -20.512,-63.171 ; -0.232,-72.134 -40.232,-72.134 ; -0.232,-63.134 -40.232,-63.134 ; -0.218,-89.993 -0.218,-63.069 ; -40.232,-72.134 -40.232,-63.134
  text "REV" at -112.232,-65.134 h1.52
  text "DOC NO" at -42.232,-65.134 h1.52
  text "SIZE" at -2.232,-65.134 h1.52
  text "PROJECTION" at -21.528,-65.482 h1.52
  text "'.ProjectRevision'" at -111.952,-70.054 h2.54
  text "PCB4259" at -44.731,-70.508 h2.54
  text "A4" at -4.882,-70.508 h2.54
  text "SHEET" at -101.232,-74.134 h1.52
  text "REF" at -2.232,-74.134 h1.52
  text "2 of 2" at -110.92,-75.106 h1.52
  text "This drawing is confidential and is supplied on the express" at -20.995,-78.741 h1.52
  text "condition that it shall not be loaned, copied or disclosed to any" at -20.995,-81.281 h1.52
  text "other person or used for any purpose without the written consent of" at -20.995,-83.821 h1.52
  text "C" at -3.672,-84.075 h2.03
  text "2017" at -8.752,-84.228 h2.54
  text "SILICON LABS" at -21.427,-88.114 h2.54
Mechanical 30:
  lines w0.2: 34.575,-63.069 34.575,-42.23 154.575,-42.23 ; 34.575,-59.134 74.575,-59.134 ; 34.575,-55.134 74.575,-55.134 154.575,-55.135 ; 34.575,-51.134 74.575,-51.134 ; 74.575,-47.134 154.575,-47.134 ; 74.581,-63.069 74.581,-42.23 ; 74.581,-42.219 74.581,-35 154.625,-35
  text "BRD4259A: EFR32FG14 2.4 GHz/434 MHz 10 dBm" at 76,-38 h1.8
  text "CUSTOMER" at 75.683,-44.146 h1.27
  text "PROJECT NO" at 36.059,-45.162 h1.52
  text "SILICON LABS" at 93.125,-46 h2.5
  text "DRAWING TITLE" at 75.912,-49.074 h1.52
  text "BRD4259" at 36.053,-49.25 h2.1
  text "DATE" at 36.059,-53.29 h1.52
  text "EFR32 Dual Band Radio Board" at 75.825,-53.325 h1.8
  text "'.Print_Date'" at 54.347,-54.306 h1.52
  text "SHEET NAME" at 75.709,-57.227 h1.52
  text "DRAWN" at 36.059,-57.354 h1.52
  text "CHECK" at 36.059,-61.418 h1.52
